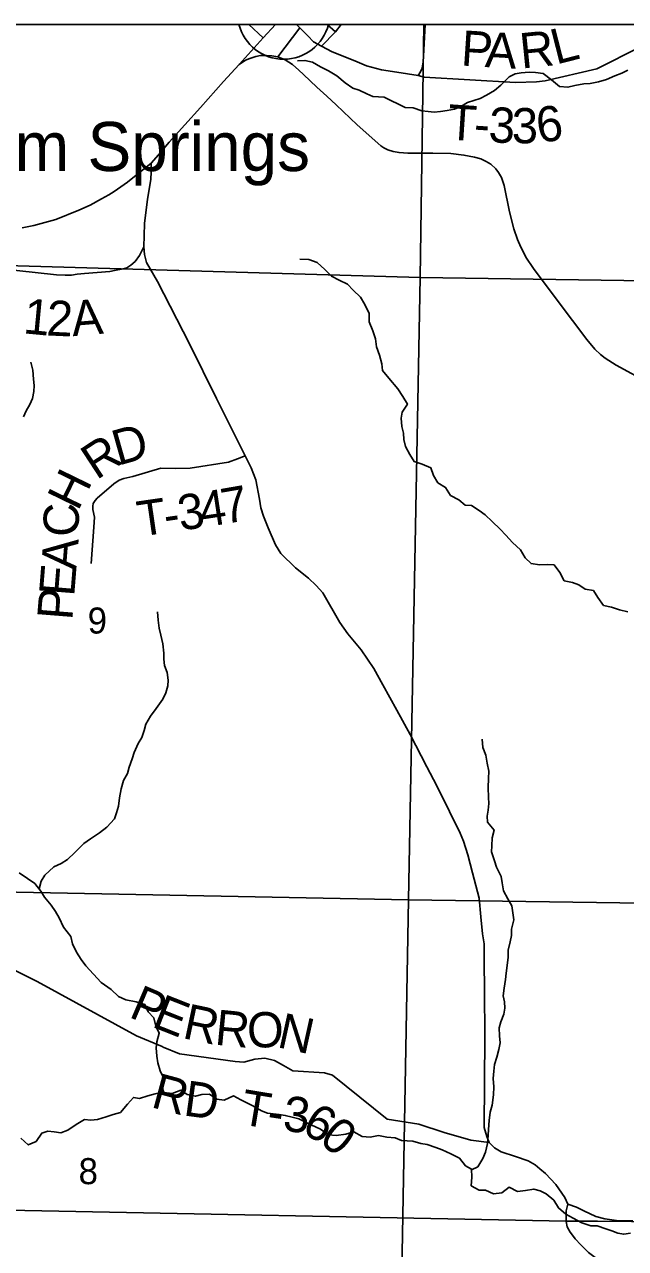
# Model space of a CAD drawing. Extents: x -20.5 to 34, y -66 to 23.9.
# Drawn here: x 4.312 to 5.279, y 18.93 to 20.9 of the extents above; entities that cross this region are included whole.
import ezdxf

# ---------------------------------------------------------------- set-up
doc = ezdxf.new("R2010")
doc.units = 0
for name, color, linetype in [('Default', 7, 'Continuous'), ('GM_X_County_Text', 7, 'Continuous'), ('GM_X_Minor_Lake', 7, 'Continuous'), ('GM_X_Minor_River_Text', 7, 'Continuous'), ('GM_X_Section_Text', 7, 'Continuous'), ('GM_X_State_Route', 7, 'Continuous'), ('GM_X_State_Shield', 7, 'Continuous'), ('GM_X_Township_Road', 7, 'Continuous'), ('GM_X_Township_Road_Text', 7, 'Continuous'), ('GM_X_Township_Text', 7, 'Continuous'), ('SH_Cut_Line', 7, 'Continuous'), ('SH_Data', 7, 'Continuous')]:
    doc.layers.add(name, color=color, linetype=linetype)

msp = doc.modelspace()

# ---------------------------------------------------------------- linework, layer by layer
at = {"layer": 'Default'}
msp.add_line((4.8015, 20.9), (4.6573, 20.9), dxfattribs=at)
for points in [[(2.1, 20.9), (8.9, 20.9), (8.9, 14.1), (2.1, 14.1)], [(4.9548, 20.9), (3.9378, 20.9), (3.9312, 20.5222), (4.9488, 20.4926)], [(5.9729, 20.9), (4.9548, 20.9), (4.9488, 20.4926), (5.968, 20.4777)]]:
    msp.add_lwpolyline(points, close=True, dxfattribs=at)
for points in [[(8.3774, 18.8452), (8.7292, 18.8379), (8.9, 18.8361), (8.9, 20.9), (2.1, 20.9), (2.1, 19.024), (2.1138, 19.0238), (2.8866, 19.0123), (2.9847, 19.0125), (3.3332, 19.0103), (5.1839, 18.9738), (5.2343, 18.9736), (5.2893, 18.9731), (5.9456, 18.969), (5.9451, 18.8918), (6.0429, 18.8899), (6.0928, 18.889), (6.2064, 18.8869)], [(6.2064, 18.8869), (6.0928, 18.889), (6.0429, 18.8899), (5.9451, 18.8918), (5.9456, 18.969), (5.2893, 18.9731), (5.2343, 18.9736), (5.1839, 18.9738), (3.3332, 19.0103), (2.9847, 19.0125), (2.8866, 19.0123), (2.8861, 18.9025), (2.8826, 18.5075), (2.8801, 18.0269), (2.88, 18.0245)]]:
    msp.add_lwpolyline(points, dxfattribs=at)
msp.add_arc((4.7294, 20.9184), 0.0744, 194.3448, 345.6552, dxfattribs=at)
at = {"layer": 'GM_X_County_Text'}
for p, q in [((4.6966, 20.8786), (4.6733, 20.9)), ((4.72, 20.8478), (4.7554, 20.8946)), ((4.7995, 20.9), (4.8126, 20.8883))]:
    msp.add_line(p, q, dxfattribs=at)
for points in [[(4.7501, 20.9), (4.7554, 20.8946), (4.7681, 20.8819), (4.7774, 20.8722), (4.7905, 20.865), (4.8076, 20.8561), (4.844, 20.8413), (4.8627, 20.8332), (4.8866, 20.8271), (4.9115, 20.8231), (4.9459, 20.818)], [(4.7905, 20.865), (4.8126, 20.8883), (4.8218, 20.9)], [(4.9459, 20.818), (4.9496, 20.824), (4.9521, 20.8299), (4.9536, 20.8397), (4.9543, 20.849), (4.9573, 20.9)], [(4.9459, 20.818), (4.9557, 20.8151), (5.1026, 20.8066), (5.1363, 20.8076), (5.15, 20.8095), (5.2334, 20.8288), (5.3038, 20.8638), (5.3498, 20.8773), (5.3902, 20.8851)], [(4.6673, 20.2059), (4.655, 20.2008), (4.6405, 20.1957), (4.5791, 20.186), (4.5547, 20.185), (4.5318, 20.186), (4.4868, 20.1724), (4.472, 20.1692), (4.4648, 20.1663), (4.4562, 20.1606), (4.4295, 20.1375), (4.4262, 20.1338), (4.4231, 20.129), (4.4224, 20.1245), (4.4225, 20.1192), (4.4249, 20.1067), (4.424, 20.0907), (4.4194, 20.0325)], [(4.5355, 19.254), (4.5337, 19.2547), (4.4928, 19.272), (4.3325, 19.3596), (4.1651, 19.4428), (4.0724, 19.4774), (4.055, 19.4834), (4.0413, 19.4858), (4.0152, 19.4898), (3.9166, 19.4987), (3.8884, 19.5055), (3.8875, 19.5055)], [(5.0598, 19.1006), (5.0303, 19.1044), (4.9876, 19.1164), (4.9471, 19.1299), (4.8958, 19.138), (4.8078, 19.2085), (4.7952, 19.2123), (4.7442, 19.216), (4.7292, 19.2243), (4.7145, 19.2326), (4.6992, 19.2359), (4.6829, 19.2343), (4.6652, 19.2299), (4.6512, 19.231), (4.5616, 19.243), (4.5355, 19.254)]]:
    msp.add_lwpolyline(points, dxfattribs=at)
at = {"layer": 'GM_X_Minor_Lake'}
for points in [[(3.9312, 20.5222), (4.9488, 20.4926), (4.9304, 19.491), (3.9151, 19.5111)], [(5.968, 20.4777), (5.9663, 20.3996), (5.9508, 19.4767), (4.9304, 19.491), (4.9488, 20.4926)], [(3.9151, 19.5111), (4.9304, 19.491), (4.9118, 18.4742), (3.8987, 18.493)], [(4.9304, 19.491), (5.9508, 19.4767), (5.9493, 19.3913), (5.9332, 18.4574), (4.9118, 18.4742)]]:
    msp.add_lwpolyline(points, close=True, dxfattribs=at)
at = {"layer": 'GM_X_Minor_River_Text'}
for points in [[(4.8909, 20.7828), (4.8731, 20.7841), (4.8632, 20.7885), (4.8506, 20.7944), (4.8407, 20.7977), (4.8281, 20.8058), (4.8147, 20.8174), (4.8017, 20.8252), (4.7887, 20.8318), (4.7758, 20.8392), (4.7636, 20.8421), (4.7515, 20.8415)], [(5.2832, 20.8262), (5.2734, 20.8218), (5.2621, 20.8175), (5.2489, 20.8116), (5.2361, 20.8076), (5.2224, 20.805), (5.2126, 20.8045), (5.1978, 20.8016), (5.1868, 20.7988), (5.1731, 20.8001), (5.1601, 20.8108), (5.147, 20.8212), (5.1344, 20.8226), (5.1245, 20.8232), (5.1116, 20.8222), (5.1018, 20.8205), (5.092, 20.8158), (5.0789, 20.8023), (5.0685, 20.7938), (5.0557, 20.786), (5.0455, 20.7809), (5.0251, 20.7745), (5.0153, 20.7686), (5.0044, 20.7639), (4.9923, 20.7614), (4.9817, 20.7597), (4.9718, 20.7588), (4.962, 20.7597), (4.9517, 20.7611), (4.9376, 20.7658), (4.925, 20.7663), (4.8909, 20.7828)], [(4.8985, 20.3309), (4.8886, 20.3432), (4.8874, 20.3535), (4.8834, 20.3678), (4.879, 20.381), (4.8773, 20.3939), (4.8726, 20.4067), (4.8667, 20.4214), (4.8669, 20.4347), (4.8602, 20.449), (4.8532, 20.4611), (4.841, 20.4723), (4.8321, 20.482), (4.8188, 20.4883), (4.8066, 20.4949), (4.7958, 20.5058), (4.7832, 20.5166), (4.7699, 20.5217), (4.7555, 20.5223)], [(4.3106, 20.2684), (4.315, 20.278), (4.3209, 20.2883), (4.3253, 20.2982), (4.3274, 20.3093), (4.328, 20.3187), (4.3271, 20.329), (4.3257, 20.3434), (4.3225, 20.3562)], [(4.9211, 20.3011), (4.9133, 20.3135), (4.8985, 20.3309)], [(5.2834, 19.9543), (5.2697, 19.9575), (5.2567, 19.9618), (5.2441, 19.9646), (5.2348, 19.9774), (5.2278, 19.989), (5.2145, 19.9911), (5.2041, 19.9981), (5.1942, 20.0017), (5.1808, 20.0045), (5.1738, 20.0181), (5.1644, 20.0301), (5.1542, 20.031), (5.1413, 20.0301), (5.1276, 20.0321), (5.1179, 20.0414), (5.1105, 20.0542), (5.0974, 20.0661), (5.0866, 20.0777), (5.0777, 20.0874), (5.0649, 20.1001), (5.0537, 20.1109), (5.0438, 20.1176), (5.0318, 20.1258), (5.0216, 20.1263), (5.0112, 20.1349), (4.9978, 20.1419), (4.99, 20.1547), (4.9777, 20.1624), (4.9707, 20.1741), (4.9663, 20.1865), (4.9525, 20.192), (4.9392, 20.1963), (4.9325, 20.208), (4.9255, 20.2207), (4.923, 20.2321), (4.9221, 20.2419), (4.9196, 20.2529), (4.9182, 20.2665), (4.92, 20.276), (4.9285, 20.2887), (4.9211, 20.3011)], [(4.3358, 19.5089), (4.339, 19.521), (4.3449, 19.5306), (4.3595, 19.5441), (4.3711, 19.5495), (4.3816, 19.5557), (4.3932, 19.5673), (4.4081, 19.5815), (4.4186, 19.5892), (4.4328, 19.5989), (4.4448, 19.6082), (4.4571, 19.6213), (4.4603, 19.6312), (4.4636, 19.6418), (4.4653, 19.6551), (4.4677, 19.6699), (4.4717, 19.6829), (4.4779, 19.6944), (4.4808, 19.7046), (4.4855, 19.718), (4.4888, 19.7283), (4.4954, 19.7428), (4.5013, 19.7523), (4.5049, 19.7634), (4.5078, 19.7737), (4.5152, 19.7866), (4.5241, 19.7989), (4.5352, 19.8139), (4.5396, 19.8242), (4.5428, 19.8352), (4.5438, 19.8447), (4.5417, 19.8568), (4.5374, 19.8681), (4.5365, 19.8783), (4.5364, 19.8882), (4.535, 19.903), (4.5318, 19.917), (4.529, 19.9283), (4.5276, 19.9412), (4.5263, 19.9544)], [(5.1, 19.4589), (5.0966, 19.4814), (5.0903, 19.4927), (5.0829, 19.5055), (5.0812, 19.5184), (5.0791, 19.5286), (5.072, 19.5436), (5.0688, 19.5538), (5.0636, 19.5682), (5.0646, 19.5777), (5.0648, 19.5909), (5.068, 19.6031), (5.0575, 19.6162), (5.0566, 19.6257), (5.0583, 19.6352), (5.0596, 19.6463), (5.0591, 19.6557), (5.0585, 19.672), (5.059, 19.6861), (5.0595, 19.6979), (5.057, 19.7111), (5.0545, 19.724), (5.0498, 19.7364), (5.0488, 19.7497)], [(4.3749, 19.447), (4.3683, 19.4619), (4.3621, 19.4724), (4.3551, 19.4822), (4.3447, 19.4953), (4.3389, 19.5051), (4.3289, 19.5175), (4.3174, 19.5253), (4.304, 19.5342)], [(4.9191, 19.1035), (4.909, 19.1078), (4.8954, 19.1091), (4.8821, 19.1115), (4.8685, 19.1087), (4.8556, 19.1103), (4.8423, 19.1173), (4.8294, 19.1137), (4.814, 19.1115), (4.8015, 19.1128), (4.7888, 19.1221), (4.7735, 19.129), (4.7636, 19.1334), (4.7537, 19.1385), (4.7431, 19.141), (4.732, 19.1439), (4.7222, 19.1452), (4.7036, 19.1475), (4.6937, 19.1512), (4.6799, 19.1596), (4.67, 19.164), (4.6604, 19.1692), (4.6486, 19.1754), (4.6336, 19.1687), (4.6218, 19.1704), (4.6103, 19.1782), (4.5978, 19.1776), (4.5873, 19.1747), (4.574, 19.1779), (4.564, 19.1846), (4.5501, 19.179), (4.5364, 19.1811), (4.5336, 19.1909), (4.536, 19.2046), (4.5305, 19.2158), (4.5269, 19.2287), (4.5252, 19.2392), (4.5242, 19.2529), (4.5252, 19.2624), (4.5291, 19.2761), (4.5236, 19.2874), (4.5204, 19.301), (4.5115, 19.3107), (4.506, 19.3223), (4.4923, 19.327), (4.4756, 19.3301), (4.4634, 19.3356), (4.4518, 19.3464), (4.4357, 19.3579), (4.411, 19.3847), (4.4033, 19.3948), (4.3959, 19.4069), (4.3896, 19.42), (4.3868, 19.4317), (4.3749, 19.447)], [(5.0318, 19.0562), (5.0416, 19.0613), (5.0501, 19.0747), (5.0541, 19.0846), (5.0573, 19.0987), (5.0586, 19.112), (5.0589, 19.1215), (5.0601, 19.1359), (5.0618, 19.1492), (5.0651, 19.1606), (5.0671, 19.177), (5.0673, 19.1899), (5.0667, 19.2035), (5.0673, 19.2153), (5.0686, 19.2259), (5.0722, 19.2377), (5.0754, 19.2503), (5.0775, 19.261), (5.0766, 19.2723), (5.0764, 19.2852), (5.0789, 19.2947), (5.0836, 19.3069), (5.085, 19.3164), (5.0845, 19.3267), (5.0828, 19.3365), (5.0841, 19.3487), (5.0862, 19.3627), (5.0872, 19.373), (5.0892, 19.3855), (5.0906, 19.3988), (5.0908, 19.4102), (5.0936, 19.4232), (5.0961, 19.4334), (5.0959, 19.4437), (5.1, 19.4589)], [(4.5361, 19.1822), (4.5228, 19.1789), (4.5108, 19.1757), (4.4976, 19.1713), (4.4877, 19.173), (4.4781, 19.1623), (4.4666, 19.1488), (4.4549, 19.1452), (4.4436, 19.1416), (4.4297, 19.1372), (4.4191, 19.1362), (4.4089, 19.1372), (4.3954, 19.1294), (4.3823, 19.1201), (4.371, 19.1157), (4.36, 19.1178), (4.3498, 19.1187), (4.34, 19.1152), (4.3311, 19.1018), (4.3183, 19.0966), (4.3064, 19.1074)], [(5.2873, 18.9546), (5.2767, 18.9526), (5.2669, 18.9547), (5.2574, 18.9584), (5.2479, 18.9616), (5.2338, 18.9663), (5.2239, 18.9662), (5.2091, 18.9709), (5.1954, 18.9787), (5.1832, 18.9849), (5.1717, 18.995), (5.1639, 19.0078), (5.1516, 19.0178), (5.1421, 19.0226), (5.1318, 19.0255), (5.1183, 19.023), (5.1058, 19.0217), (5.0921, 19.0283), (5.0805, 19.0194), (5.0669, 19.0177), (5.0543, 19.0239), (5.0441, 19.0234), (5.0311, 19.0308), (5.032, 19.0444), (5.0318, 19.0573), (5.0219, 19.0629), (5.0123, 19.0749), (4.9982, 19.0822), (4.9844, 19.0888), (4.9742, 19.0921), (4.9601, 19.0972), (4.9502, 19.0989), (4.9373, 19.1025), (4.9191, 19.1035)]]:
    msp.add_lwpolyline(points, dxfattribs=at)
at = {"layer": 'GM_X_State_Route'}
msp.add_line((4.5164, 20.6765), (4.5281, 20.6904), dxfattribs=at)
for points in [[(4.6579, 20.8357), (4.6966, 20.8786), (4.7165, 20.9)], [(4.5281, 20.6904), (4.5449, 20.7104), (4.5955, 20.7665), (4.6326, 20.8082), (4.6579, 20.8357)], [(5.1975, 18.9467), (5.1903, 18.9563), (5.1858, 18.9647), (5.1841, 18.9733), (5.184, 18.9906), (5.1866, 19.0009), (5.1817, 19.0118), (5.1674, 19.0326), (5.1509, 19.0507), (5.1418, 19.0582), (5.1341, 19.0643), (5.1226, 19.0711), (5.1025, 19.0778), (5.0796, 19.0854), (5.0685, 19.0918), (5.0598, 19.1006), (5.0561, 19.1103), (5.052, 19.1247), (5.0531, 19.2701), (5.0531, 19.2994), (5.0524, 19.3168), (5.0519, 19.4204), (5.0494, 19.4364), (5.0469, 19.4636), (5.0437, 19.4938), (5.0334, 19.5344), (5.0259, 19.5633), (5.0189, 19.5852), (5.0133, 19.5984), (4.9964, 19.6332), (4.9758, 19.6747), (4.96, 19.7053), (4.9328, 19.7573), (4.9116, 19.7965), (4.8889, 19.8368), (4.8743, 19.8633), (4.8543, 19.8936), (4.8329, 19.9192), (4.8197, 19.9374), (4.7923, 19.9853), (4.7819, 19.9971), (4.7695, 20.009), (4.7482, 20.0252), (4.7246, 20.0485), (4.7164, 20.0625), (4.7047, 20.0895), (4.6968, 20.1085), (4.6929, 20.1222), (4.6907, 20.1359), (4.6848, 20.1672), (4.6772, 20.1863), (4.6673, 20.2059), (4.6215, 20.2979), (4.5779, 20.3861), (4.5264, 20.4861), (4.5086, 20.517), (4.5054, 20.5298), (4.5042, 20.542), (4.5048, 20.5601), (4.5055, 20.5797), (4.5103, 20.6186), (4.5159, 20.6504), (4.516, 20.6629), (4.5164, 20.6765)], [(4.5042, 20.542), (4.4975, 20.5279), (4.4907, 20.5186), (4.4837, 20.5128), (4.4772, 20.5081), (4.4685, 20.5062), (4.4571, 20.5042), (4.4497, 20.5024), (4.4091, 20.4992), (4.3969, 20.4979), (4.3878, 20.4967), (4.3777, 20.4963), (4.3639, 20.4968), (4.2699, 20.507), (4.1797, 20.5131), (4.1131, 20.5179), (4.0245, 20.5214), (4.0161, 20.5239), (3.9958, 20.5385), (3.985, 20.5535), (3.9843, 20.5773), (3.9751, 20.594), (3.9566, 20.6245), (3.9473, 20.6414)], [(5.1866, 19.0009), (5.2004, 18.9962), (5.2123, 18.9906), (5.2318, 18.9813), (5.2463, 18.9776), (5.2651, 18.9747), (5.2914, 18.9741)], [(5.2682, 18.8977), (5.2559, 18.9034), (5.2425, 18.9094), (5.2307, 18.9155), (5.22, 18.9235), (5.2074, 18.9357), (5.1986, 18.9451), (5.1975, 18.9467)]]:
    msp.add_lwpolyline(points, dxfattribs=at)
at = {"layer": 'GM_X_Township_Road'}
msp.add_line((4.5281, 20.6904), (4.5164, 20.6765), dxfattribs=at)
for points in [[(4.7539, 20.8262), (4.7434, 20.8356), (4.7317, 20.8428), (4.72, 20.8478), (4.7102, 20.8494), (4.7016, 20.8501), (4.6923, 20.8498), (4.6846, 20.8484), (4.6751, 20.8453), (4.668, 20.8425), (4.6579, 20.8357)], [(4.6579, 20.8357), (4.6326, 20.8082), (4.5955, 20.7665), (4.5449, 20.7104), (4.5281, 20.6904)], [(5.1178, 20.5282), (5.1109, 20.5416), (5.1058, 20.5541), (5.0997, 20.5711), (5.0926, 20.5985), (5.0844, 20.6406), (5.0799, 20.6539), (5.0749, 20.6617), (5.0706, 20.6677), (5.0628, 20.6751), (5.0553, 20.6795), (5.0468, 20.6835), (5.0367, 20.6865), (5.0194, 20.6897), (4.9982, 20.6924), (4.9692, 20.693), (4.929, 20.6928), (4.9152, 20.6938), (4.9054, 20.6955), (4.8972, 20.6981), (4.8904, 20.7016), (4.8858, 20.7048), (4.8476, 20.7386), (4.8141, 20.7704), (4.7987, 20.7847), (4.7827, 20.799), (4.7613, 20.8195), (4.7539, 20.8262)], [(4.5164, 20.6765), (4.4779, 20.6461), (4.4566, 20.631), (4.4482, 20.6259), (4.4363, 20.6192), (4.4178, 20.6092), (4.3996, 20.6011), (4.3626, 20.5858), (4.3276, 20.5765), (4.3088, 20.5727)], [(5.3195, 20.3217), (5.2642, 20.3517), (5.2466, 20.3629), (5.2391, 20.369), (5.2301, 20.3772), (5.217, 20.3927), (5.1713, 20.4542), (5.1315, 20.507), (5.1192, 20.5255), (5.1178, 20.5282)]]:
    msp.add_lwpolyline(points, dxfattribs=at)
at = {"layer": 'SH_Cut_Line'}
msp.add_lwpolyline([(8.0662, 14.9881), (8.0784, 15.8902), (8.0825, 16.3121), (8.087, 16.6605), (8.0955, 17.3258), (8.2289, 17.3235), (8.271, 17.3227), (8.5216, 17.3182), (8.9, 17.3115), (8.9, 20.9), (2.1, 20.9), (2.1, 14.4131)], dxfattribs=at)
at = {"layer": 'SH_Data'}
msp.add_line((2.1, 20.9), (8.9, 20.9), dxfattribs=at)

# ---------------------------------------------------------------- texts
at = {"layer": 'GM_X_Section_Text'}
for s, rotation, p in [('P', 356.2959, (5.0137, 20.834)), ('A', 356.7705, (5.0525, 20.8315)), ('R', 5.7832, (5.1121, 20.8289)), ('L', 14.3385, (5.1677, 20.8352)), ('T', 356.3483, (4.9918, 20.7149)), ('3', 356.9311, (5.0582, 20.7107)), ('3', 359.9612, (5.0964, 20.7087)), ('6', 7.6143, (5.1396, 20.7092)), ('-', 356.4618, (5.0344, 20.7121)), ('D', 15.8336, (4.4631, 20.1896)), ('R', 33.1742, (4.4282, 20.1659)), ('H', 64.0125, (4.3984, 20.1154)), ('7', 9.8904, (4.6341, 20.0957)), ('T', 8.2659, (4.498, 20.0755)), ('3', 8.3678, (4.5632, 20.085)), ('4', 8.689, (4.5982, 20.0902)), ('C', 89.8028, (4.3998, 20.0753)), ('-', 8.2866, (4.54, 20.0816)), ('A', 85.4721, (4.3956, 20.0208)), ('E', 85.4223, (4.3922, 19.9783)), ('P', 85.4242, (4.3892, 19.9401)), ('P', 336.875, (4.4786, 19.303)), ('E', 338.4541, (4.5154, 19.2873)), ('R', 348.0938, (4.5649, 19.2687)), ('R', 354.3556, (4.6173, 19.258)), ('O', 0.7707, (4.6707, 19.2531)), ('N', 347.503, (4.7172, 19.2542)), ('R', 345.0483, (4.5142, 19.1577)), ('D', 352.1754, (4.5667, 19.1442)), ('T', 350.6088, (4.6578, 19.1302)), ('3', 354.4659, (4.7269, 19.1192)), ('6', 330.3358, (4.7558, 19.1177)), ('-', 351.3234, (4.7005, 19.1231)), ('0', 321.6645, (4.7843, 19.1016))]:
    msp.add_text(s, height=0.0568, rotation=rotation, dxfattribs=at).set_placement(p)
at = {"layer": 'GM_X_State_Shield'}
msp.add_text('Harlem Springs', height=0.078977, rotation=0, dxfattribs=at).set_placement((4.044, 20.6641))
at = {"layer": 'GM_X_Township_Road_Text'}
for s, rotation, p in [('1', 354.6332, (4.3091, 20.403)), ('2', 357.3947, (4.3469, 20.3995)), ('A', 4.8796, (4.39, 20.3981))]:
    msp.add_text(s, height=0.0568, rotation=rotation, dxfattribs=at).set_placement(p)
at = {"layer": 'GM_X_Township_Text'}
for s, p in [('9', (4.414, 19.9196)), ('8', (4.3994, 19.0333))]:
    msp.add_text(s, height=0.0419, rotation=0, dxfattribs=at).set_placement(p)

doc.saveas('drawing.dxf')
